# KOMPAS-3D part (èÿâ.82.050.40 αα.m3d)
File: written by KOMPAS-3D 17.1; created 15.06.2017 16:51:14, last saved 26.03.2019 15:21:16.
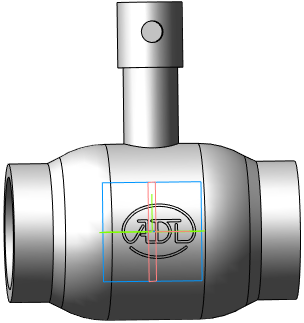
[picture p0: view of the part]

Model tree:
1. Операция без истории:2  (labels: Сталь 20  ГОСТ 1050-88)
